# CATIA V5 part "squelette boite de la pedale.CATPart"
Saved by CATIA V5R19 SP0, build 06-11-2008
Part number: squelette boite de la pedale
Bounding box of the stored display mesh (mm): x 0 to 0, y -40 to 0, z 0 to 0
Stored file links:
  D:\ifma\cfao\FINI\squelette boite de la pedale.CATPart
  D:\ifma\cfao\FINI\velo pliant.CATProduct
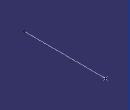
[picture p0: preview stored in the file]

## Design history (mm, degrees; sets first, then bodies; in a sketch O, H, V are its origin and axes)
Set1
  Point1: linked copy from another document
  Plane1: linked copy from another document
Set2
  Point2: (0, 0, 0)
  Line1: type PtDir, Direction (0, 1, 0), Start 0, End 40, RefPoint Point2
  Plane2: type Offset, Offset 0, RefPlane Plane1
Body1 (main body)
